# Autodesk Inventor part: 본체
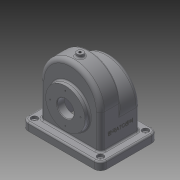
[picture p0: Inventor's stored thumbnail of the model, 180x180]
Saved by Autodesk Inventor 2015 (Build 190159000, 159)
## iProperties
Created: 2017-11
Part Number: 본체
Material: 일반
Document SubType Name: Modeling
Designer: 2-PC10
Density: 1 g/cm^3
Appearance: 기본값
Mass: 398.334 g
Surface Area: 1182.07 cm^2
Volume: 398.334 cm^3
Author: 2-PC10
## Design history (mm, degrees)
sketch "스케치1"
  geometry: L1 (-75, 55)-(75, 55); L2 (75, 55)-(75, -55); L3 (75, -55)-(-75, -55); L4 (-75, -55)-(-75, 55); L5 (-75, 55)-(75, -55); L6 (75, 55)-(-75, -55); 1 further point
  constraints: 12 end point, 2 midpoint, 2 parallel, 1 horizontal, 1 perpendicular
  dimensions: "d0" = 110 distance between parallel lines of L3 L1; "d1" = 150 distance between parallel lines of L2 L4
extrude "돌출1" new body sketch "스케치1" distance "d2" = 15; taper "d3" = 0 deg
sketch "스케치2"
  geometry: L1 (58, 80)-(58, 15); L2 (-58, 80)-(-58, 15); L3 (-75, 15)-(75, 15) reference; L4 (75, 0)-(-75, 0) reference; A1 r 58 centre (0, 80) between (-58, 80) and (58, 80); 1 further point
  constraints: 4 end point, 2 point on circle, 2 point on line, 2 tangent, 2 vertical, 1 centre point, 1 vertical alignment
  dimensions: "d5" = 58 radius of A1; "d6" = 80 distance from line of L4 A1.centre
extrude "돌출2" join sketch "스케치2" stored distance "d7" = 76; taper "d8" = 0 deg
sketch "스케치3"
  geometry: L1 (75, 0)-(-75, 0) reference; C1 r 37.5 at (0, 65); 2 further points
  constraints: 1 centre point, 1 midpoint, 1 vertical alignment
  dimensions: "d9" = 75 diameter of C1; "d10" = 65 distance from line of L1 C1.centre
extrude "돌출3" join sketch "스케치3" distance "d11" = 9; taper "d12" = 0 deg
sketch "스케치4"
  geometry: L1 (-75, 0)-(75, 0) reference; C1 r 31 at (0, -65); 2 further points
  constraints: 1 centre point, 1 midpoint, 1 vertical alignment
  dimensions: "d13" = 62 diameter of C1; "d14" = 65 distance from line of L1 C1.centre
extrude "돌출4" join sketch "스케치4" distance "d15" = 10; taper "d16" = 0 deg
sketch "스케치5"
  geometry: L1 (75, 0)-(-75, 0) reference; L2 (58, -15)-(58, -80) reference; L3 (-58, -80)-(-58, -15) reference; A1 r 58 centre (0, -57) between (-58, -57) and (58, -57); A2 r 58 centre (0, -80) between (-58, -80) and (58, -80) reference; 1 further point
  constraints: 2 point on circle, 2 point on line, 1 centre point, 1 midpoint, 1 vertical alignment
  dimensions: "d22" = 58 radius of A1; "d23" = 57 distance from line of L1 A1.centre
extrude "돌출5" cut sketch "스케치5" distance "d24" = 38; taper "d25" = 0 deg
sketch "스케치6"
  geometry: L1 (-53, -33)-(53, -33); L2 (53, -33)-(53, 33); L3 (53, 33)-(-53, 33); L4 (-53, 33)-(-53, -33); L5 (-53, -33)-(53, 33); L6 (53, -33)-(-53, 33); 1 further point
  constraints: 12 end point, 2 midpoint, 2 parallel, 1 horizontal, 1 perpendicular
  dimensions: "d26" = 66 distance between parallel lines of L3 L1; "d27" = 106 distance between parallel lines of L2 L4
extrude "돌출6" cut sketch "스케치6" distance "d28" = 15; taper "d29" = 0 deg
hole "구멍1" diameter "d33" = 32; stored, may be unused: countersink angle "d37" = 90 deg, drill point angle "d39" = 118 deg; dims "d31" = 10, "d32" = 10, "d34" = 6, "d35" = 4, "d36" = 2, "d38" = 8
node "작업 평면2"
sketch "스케치8"
  geometry: L1 (-53, -15)-(53, -15) reference; L2 (53, -57)-(53, -15); L3 (-53, -57)-(-53, -15); A1 r 58 centre (0, -57) between (-58, -57) and (58, -57) reference; A2 r 53 centre (0, -57) between (-53, -57) and (53, -57); 1 further point
  constraints: 4 end point, 2 perpendicular, 2 point on circle, 1 centre point, 1 coincident
  dimensions: "d43" = 53 radius of A2
extrude "돌출7" cut sketch "스케치8" distance "d44" = 40; taper "d45" = 0 deg
node "작업 평면3"
sketch "스케치9"
  geometry: L1 (53, -80)-(53, -15); L2 (-53, -80)-(-53, -15); L3 (53, -15)-(-53, -15); A1 r 53 centre (0, -80) between (-53, -80) and (53, -80); 1 further point
  constraints: 6 end point, 2 point on circle, 2 vertical, 1 centre point, 1 horizontal, 1 tangent
  dimensions: "d47" = 53 radius of A1; "d48" = 80 distance of point (0, 0) A1.centre
extrude "돌출8" cut sketch "스케치9" distance "d49" = 28; taper "d50" = 0 deg
sketch "스케치10"
  geometry: C1 r 37.5 at (0, 0) reference; A1 r 29 centre (0, 0) between (0, 29) and (-29, 0); 3 further points
  constraints: 4 point on circle, 2 horizontal alignment, 2 vertical alignment, 1 centre point, 1 coincident
  dimensions: "d51" = 58 diameter of A1
hole "구멍2" sketch "스케치10" at (0, 29), (-29, 0), (0, -29), (29, 0) diameter "d52" = 2.459; stored, may be unused: countersink angle "d56" = 90 deg, drill point angle "d58" = 118 deg; dims "d53" = 6, "d54" = 4, "d55" = 2, "d57" = 8
sketch "스케치11"
  geometry: C1 r 31 at (0, 0) reference; A1 r 26 centre (0, 0) between (0, -26) and (26, 0); 3 further points
  constraints: 4 point on circle, 2 horizontal alignment, 2 vertical alignment, 1 centre point, 1 coincident
  dimensions: "d59" = 52 diameter of A1
hole "구멍3" sketch "스케치11" at (0, -26), (26, 0), (0, 26), (-26, 0) diameter "d60" = 2.459; stored, may be unused: countersink angle "d64" = 90 deg, drill point angle "d66" = 118 deg; dims "d61" = 6, "d62" = 4, "d63" = 2, "d65" = 8
node "작업 평면4"
sketch "스케치13"
  geometry: L1 (-58, -38)-(58, -38) reference; C1 r 6 at (0, -19); 1 further point
  constraints: 1 centre point, 1 vertical alignment
  dimensions: "d68" = 12 diameter of C1; "d69" = 19 distance from line of L1 C1.centre
extrude "돌출9" join sketch "스케치13" stored distance "d70" = 28; taper "d71" = 0 deg
fillet "모깎기1" dims "d72" = 12
hole "구멍4" diameter "d75" = 12; stored, may be unused: countersink angle "d79" = 90 deg, drill point angle "d81" = 0 deg; dims "d73" = 10, "d74" = 10, "d76" = 6, "d77" = 4, "d78" = 2, "d80" = 5
hole "구멍5" diameter "d84" = 12; stored, may be unused: countersink angle "d88" = 90 deg, drill point angle "d90" = 0 deg; dims "d82" = 10, "d83" = 10, "d85" = 6, "d86" = 4, "d87" = 2, "d89" = 5
hole "구멍6" diameter "d93" = 12; stored, may be unused: countersink angle "d97" = 90 deg, drill point angle "d99" = 0 deg; dims "d91" = 10, "d92" = 10, "d94" = 6, "d95" = 4, "d96" = 2, "d98" = 5
hole "구멍7" diameter "d102" = 12; stored, may be unused: countersink angle "d106" = 90 deg, drill point angle "d108" = 0 deg; dims "d100" = 10, "d101" = 10, "d103" = 6, "d104" = 4, "d105" = 2, "d107" = 5
hole "구멍8" diameter "d111" = 5; stored, may be unused: countersink angle "d115" = 90 deg, drill point angle "d117" = 0 deg; dims "d109" = 10, "d110" = 10, "d112" = 6, "d113" = 4, "d114" = 2, "d116" = 5
hole "구멍9" diameter "d120" = 5; stored, may be unused: countersink angle "d124" = 90 deg, drill point angle "d126" = 0 deg; dims "d118" = 10, "d119" = 10, "d121" = 6, "d122" = 4, "d123" = 2, "d125" = 5
hole "구멍10" diameter "d129" = 5; stored, may be unused: countersink angle "d133" = 90 deg, drill point angle "d135" = 0 deg; dims "d127" = 10, "d128" = 10, "d130" = 6, "d131" = 4, "d132" = 2, "d134" = 5
hole "구멍11" diameter "d138" = 5; stored, may be unused: countersink angle "d142" = 90 deg, drill point angle "d144" = 0 deg; dims "d136" = 10, "d137" = 10, "d139" = 6, "d140" = 4, "d141" = 2, "d143" = 5
chamfer "모따기1" distance "d145" = 1; stored, may be unused: second distance "d146" = 2, angle "d147" = 45 deg
fillet "모깎기2" dims "d148" = 3
hole "구멍12" diameter "d151" = 4.459; stored, may be unused: countersink angle "d155" = 90 deg, drill point angle "d157" = 118 deg; dims "d149" = 10, "d150" = 10, "d152" = 10, "d153" = 4, "d154" = 2, "d156" = 12.8
sketch "스케치14"
  geometry: L1 (-31.5, 13)-(-31.5, 63); L2 (-31.5, 63)-(-18.5, 63); L3 (-18.5, 63)-(-18.5, 13); L4 (-18.5, 13)-(-31.5, 13); L5 (-31.5, 38)-(-18.5, 38); L6 (-25, 63)-(-25, 13); L7 (0, 0)-(-65, 0) reference; L8 (15, 81)-(15, -5) reference; 1 further point
  constraints: 4 end point, 4 midpoint, 2 other
  dimensions: "d158" = 13 distance between parallel lines of L3 L1; "d159" = 50 distance between parallel lines of L4 L2; "d160" = 38 distance between parallel lines of L7 L5; "d161" = 40 distance between parallel lines of L8 L6
feature "엠보싱1" sketch "스케치14" dims "d9" = 75, "d10" = 65, "d162" = 0.5, "d163" = 0
fillet "모깎기4" dims "d165" = 8
fillet "모깎기5" dims "d166" = 3
node "솔리드1"
other parameters: "d20" = 58, "d41" = -5, "d46" = -5, "d67" = 144
